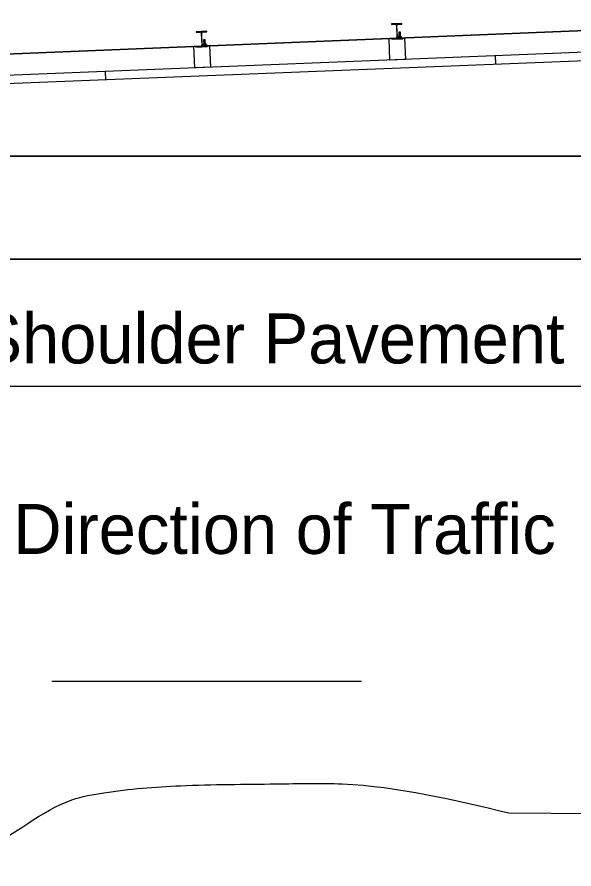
# Model space of a CAD drawing. Extents: x 8045 to 81668, y 6217 to 16762.
# Drawn here: x 11213.9 to 11392.2, y 9467.4 to 9740.2 of the extents above; entities that cross this region are included whole.
import ezdxf

# ---------------------------------------------------------------- set-up
doc = ezdxf.new("R2010")
doc.units = 0
for name, color, linetype in [('dsnStdLabel', 7, 'Continuous'), ('dsnStdNote', 7, 'Continuous'), ('dsnStdPattern', 7, 'Continuous'), ('Level 4', 7, 'Continuous')]:
    doc.layers.add(name, color=color, linetype=linetype)

msp = doc.modelspace()

# ---------------------------------------------------------------- linework, layer by layer
at = {"layer": 'dsnStdLabel'}
for p, q in [((11025.35, 9720.71), (11500.75, 9740.23)), ((11337.09, 9738.15), (11333.76, 9738.02)), ((11333.76, 9738.02), (11333.77, 9737.86)), ((11333.77, 9737.86), (11334.94, 9737.91)), ((11335.37, 9737.51), (11335.52, 9733.76)), ((11335.68, 9733.77), (11335.53, 9737.52)), ((11335.93, 9737.95), (11337.1, 9738)), ((11337.1, 9738), (11337.09, 9738.15)), ((11274.64, 9735.66), (11271.31, 9735.52)), ((11271.31, 9735.52), (11271.32, 9735.37)), ((11271.32, 9735.37), (11272.49, 9735.41)), ((11272.92, 9735.01), (11273.07, 9731.27)), ((11273.23, 9731.27), (11273.08, 9735.02)), ((11273.48, 9735.45), (11274.65, 9735.5)), ((11274.65, 9735.5), (11274.64, 9735.66)), ((11336.63, 9735.42), (11336.11, 9735.4)), ((11336.11, 9735.4), (11336.17, 9733.89)), ((11336.69, 9733.92), (11336.63, 9735.42)), ((11273.46, 9731.39), (11273.38, 9731.33)), ((11273.39, 9730.96), (11273.38, 9731.33)), ((11273.46, 9731.39), (11274.43, 9731.42)), ((11274.18, 9732.93), (11273.66, 9732.91)), ((11273.66, 9732.91), (11273.72, 9731.4)), ((11273.7, 9730.93), (11273.68, 9731.34)), ((11274.24, 9731.42), (11274.18, 9732.93)), ((11274.3, 9730.95), (11274.28, 9731.37)), ((11274.43, 9731.42), (11274.5, 9731.43)), ((11274.58, 9731.38), (11274.5, 9731.43)), ((11274.6, 9730.96), (11274.58, 9731.38)), ((11333.01, 9733.4), (11333.63, 9733.43)), ((11333.29, 9726.45), (11333.01, 9733.4)), ((11333.64, 9733.12), (11333.63, 9733.43)), ((11337.39, 9733.27), (11333.64, 9733.12)), ((11335.12, 9733.33), (11333.95, 9733.28)), ((11333.95, 9733.28), (11333.96, 9733.13)), ((11333.96, 9733.13), (11337.29, 9733.26)), ((11335.91, 9733.88), (11335.83, 9733.83)), ((11335.84, 9733.45), (11335.83, 9733.83)), ((11335.91, 9733.88), (11336.88, 9733.92)), ((11337.28, 9733.42), (11336.11, 9733.37)), ((11336.15, 9733.42), (11336.13, 9733.84)), ((11336.75, 9733.45), (11336.73, 9733.86)), ((11336.88, 9733.92), (11336.95, 9733.93)), ((11337.03, 9733.88), (11336.95, 9733.93)), ((11336.97, 9733.41), (11337.05, 9733.46)), ((11337.05, 9733.46), (11337.03, 9733.88)), ((11337.29, 9733.26), (11337.28, 9733.42)), ((11337.38, 9733.58), (11338, 9733.6)), ((11337.38, 9733.58), (11337.39, 9733.27)), ((11338, 9733.6), (11338.28, 9726.65)), ((11403.96, 9729.27), (10992.39, 9712.81)), ((11270.56, 9730.91), (11271.18, 9730.93)), ((11270.84, 9723.95), (11270.56, 9730.91)), ((11271.19, 9730.62), (11271.18, 9730.93)), ((11274.94, 9730.77), (11271.19, 9730.62)), ((11272.67, 9730.83), (11271.5, 9730.79)), ((11271.5, 9730.79), (11271.51, 9730.63)), ((11271.51, 9730.63), (11274.84, 9730.76)), ((11274.83, 9730.92), (11273.66, 9730.87)), ((11274.52, 9730.91), (11274.6, 9730.96)), ((11274.84, 9730.76), (11274.83, 9730.92)), ((11274.93, 9731.08), (11275.55, 9731.11)), ((11274.93, 9731.08), (11274.94, 9730.77)), ((11275.55, 9731.11), (11275.83, 9724.15)), ((11404.06, 9726.57), (10992.39, 9710.1)), ((11338.28, 9726.65), (11333.29, 9726.45)), ((11367.01, 9727.8), (11367.12, 9725.09)), ((11275.83, 9724.15), (11270.84, 9723.95)), ((11242.11, 9722.8), (11242.22, 9720.09)), ((10368.64, 9695.63), (11500.75, 9695.63)), ((10347.65, 9662.65), (11995.12, 9662.65)), ((11500.75, 9662.65), (10347.65, 9662.65)), ((10368.86, 9622), (11982.65, 9622)), ((11225.04, 9527.54), (11324.21, 9527.54)), ((11371.34, 9485.38), (11700.54, 9482.92))]:
    msp.add_line(p, q, dxfattribs=at)
for centre, start, end in [((11334.95, 9737.49), 2.2841, 92.2932), ((11335.94, 9737.53), 92.2981, 182.2871), ((11272.51, 9735), 2.2841, 92.2932), ((11273.49, 9735.04), 92.2981, 182.2871), ((11335.1, 9733.75), 272.2981, 2.2871), ((11336.09, 9733.79), 182.2841, 272.2932), ((11272.65, 9731.25), 272.2981, 2.2871), ((11273.64, 9731.29), 182.2841, 272.2932)]:
    msp.add_arc(centre, 0.417, start, end, dxfattribs=at)
for points in [[(11273.68, 9731.34), (11273.65, 9731.36), (11273.6, 9731.38), (11273.52, 9731.39), (11273.44, 9731.37), (11273.4, 9731.34), (11273.38, 9731.33)], [(11274.28, 9731.37), (11274.23, 9731.38), (11274.12, 9731.4), (11273.96, 9731.41), (11273.81, 9731.39), (11273.72, 9731.36), (11273.68, 9731.34)], [(11274.58, 9731.38), (11274.56, 9731.39), (11274.53, 9731.41), (11274.47, 9731.42), (11274.39, 9731.42), (11274.33, 9731.4), (11274.29, 9731.37), (11274.28, 9731.37)], [(11336.13, 9733.84), (11336.1, 9733.85), (11336.05, 9733.88), (11335.97, 9733.89), (11335.89, 9733.87), (11335.85, 9733.84), (11335.83, 9733.83)], [(11336.05, 9733.38), (11336.06, 9733.38), (11336.09, 9733.39), (11336.12, 9733.41), (11336.15, 9733.42)], [(11336.73, 9733.86), (11336.68, 9733.88), (11336.57, 9733.9), (11336.41, 9733.91), (11336.26, 9733.88), (11336.17, 9733.86), (11336.13, 9733.84)], [(11336.15, 9733.42), (11336.2, 9733.41), (11336.31, 9733.39), (11336.46, 9733.38), (11336.61, 9733.4), (11336.7, 9733.43), (11336.75, 9733.45)], [(11337.03, 9733.88), (11337.01, 9733.89), (11336.98, 9733.9), (11336.92, 9733.92), (11336.84, 9733.92), (11336.78, 9733.9), (11336.74, 9733.87), (11336.73, 9733.86)], [(11336.75, 9733.45), (11336.76, 9733.44), (11336.8, 9733.42), (11336.86, 9733.4), (11336.94, 9733.41), (11337, 9733.43), (11337.03, 9733.45), (11337.05, 9733.46)], [(11273.6, 9730.88), (11273.61, 9730.88), (11273.64, 9730.89), (11273.67, 9730.91), (11273.7, 9730.93)], [(11273.7, 9730.93), (11273.75, 9730.91), (11273.86, 9730.89), (11274.01, 9730.88), (11274.16, 9730.91), (11274.25, 9730.94), (11274.3, 9730.95)], [(11274.3, 9730.95), (11274.31, 9730.94), (11274.35, 9730.92), (11274.41, 9730.9), (11274.49, 9730.91), (11274.55, 9730.93), (11274.58, 9730.95), (11274.6, 9730.96)]]:
    msp.add_open_spline(points, degree=3, dxfattribs=at)
msp.add_spline([(10372.93, 9478.29), (10382.36, 9480.86), (10412.58, 9480.29), (10440.52, 9472.31), (10467.89, 9471.16), (10486.14, 9476.87), (10512.94, 9476.3), (10537.46, 9471.74), (10561.41, 9475.16), (10578.52, 9480.29), (10618.43, 9472.88), (10645.23, 9468.88), (10669.75, 9478.01), (10692.56, 9479.72), (10731.34, 9474.02), (10730.77, 9474.02), (10751.92, 9472.41), (10788.99, 9475.27), (10814.08, 9478.12), (10832.9, 9481.54), (10856.85, 9480.97), (10878.51, 9477.55), (10904.17, 9472.98), (10937.82, 9474.13), (10969.18, 9480.4), (10994.27, 9480.4), (11026.2, 9472.98), (11055.29, 9470.13), (11088.93, 9476.98), (11121.43, 9480.4), (11155.65, 9473.55), (11181.31, 9470.7), (11203.54, 9474.13), (11231.49, 9489.53), (11241.75, 9491.81), (11266.27, 9494.09), (11296.93, 9494.66), (11318.03, 9494.66), (11371.34, 9485.38)], degree=3, dxfattribs=at)
at = {"layer": 'dsnStdPattern'}
for p, q in [((11337.09, 9738.15), (11333.76, 9738.02)), ((11337.09, 9738.15), (11333.76, 9738.02)), ((11333.76, 9738.02), (11333.77, 9737.86)), ((11333.76, 9738.02), (11333.77, 9737.86)), ((11333.77, 9737.86), (11334.94, 9737.91)), ((11333.77, 9737.86), (11334.94, 9737.91)), ((11335.37, 9737.51), (11335.52, 9733.76)), ((11335.37, 9737.51), (11335.52, 9733.76)), ((11335.68, 9733.77), (11335.53, 9737.52)), ((11335.68, 9733.77), (11335.53, 9737.52)), ((11335.93, 9737.95), (11337.1, 9738)), ((11335.93, 9737.95), (11337.1, 9738)), ((11337.1, 9738), (11337.09, 9738.15)), ((11337.1, 9738), (11337.09, 9738.15)), ((11274.64, 9735.66), (11271.31, 9735.52)), ((11274.64, 9735.66), (11271.31, 9735.52)), ((11271.31, 9735.52), (11271.32, 9735.37)), ((11271.31, 9735.52), (11271.32, 9735.37)), ((11271.32, 9735.37), (11272.49, 9735.41)), ((11271.32, 9735.37), (11272.49, 9735.41)), ((11272.92, 9735.01), (11273.07, 9731.27)), ((11272.92, 9735.01), (11273.07, 9731.27)), ((11273.23, 9731.27), (11273.08, 9735.02)), ((11273.23, 9731.27), (11273.08, 9735.02)), ((11273.48, 9735.45), (11274.65, 9735.5)), ((11273.48, 9735.45), (11274.65, 9735.5)), ((11274.65, 9735.5), (11274.64, 9735.66)), ((11274.65, 9735.5), (11274.64, 9735.66)), ((11336.63, 9735.42), (11336.11, 9735.4)), ((11336.63, 9735.42), (11336.11, 9735.4)), ((11336.11, 9735.4), (11336.17, 9733.89)), ((11336.11, 9735.4), (11336.17, 9733.89)), ((11336.69, 9733.92), (11336.63, 9735.42)), ((11336.69, 9733.92), (11336.63, 9735.42)), ((11273.46, 9731.39), (11273.38, 9731.33)), ((11273.46, 9731.39), (11273.38, 9731.33)), ((11273.38, 9731.33), (11273.39, 9730.96)), ((11273.39, 9730.96), (11273.38, 9731.33)), ((11274.43, 9731.42), (11273.46, 9731.39)), ((11273.46, 9731.39), (11274.43, 9731.42)), ((11274.18, 9732.93), (11273.66, 9732.91)), ((11274.18, 9732.93), (11273.66, 9732.91)), ((11273.66, 9732.91), (11273.72, 9731.4)), ((11273.66, 9732.91), (11273.72, 9731.4)), ((11273.68, 9731.34), (11273.7, 9730.93)), ((11273.7, 9730.93), (11273.68, 9731.34)), ((11273.7, 9730.93), (11273.68, 9731.34)), ((11273.72, 9731.4), (11274.24, 9731.42)), ((11274.24, 9731.42), (11274.18, 9732.93)), ((11274.24, 9731.42), (11274.18, 9732.93)), ((11274.3, 9730.95), (11274.28, 9731.37)), ((11274.28, 9731.37), (11274.3, 9730.95)), ((11274.3, 9730.95), (11274.28, 9731.37)), ((11274.5, 9731.43), (11274.43, 9731.42)), ((11274.43, 9731.42), (11274.5, 9731.43)), ((11274.58, 9731.38), (11274.5, 9731.43)), ((11274.58, 9731.38), (11274.5, 9731.43)), ((11274.6, 9730.96), (11274.58, 9731.38)), ((11274.6, 9730.96), (11274.58, 9731.38)), ((11333.01, 9733.4), (11333.63, 9733.43)), ((11333.29, 9726.45), (11333.01, 9733.4)), ((11333.64, 9733.12), (11333.63, 9733.43)), ((11337.39, 9733.27), (11333.64, 9733.12)), ((11335.12, 9733.33), (11333.95, 9733.28)), ((11335.12, 9733.33), (11333.95, 9733.28)), ((11333.95, 9733.28), (11333.96, 9733.13)), ((11333.95, 9733.28), (11333.96, 9733.13)), ((11333.96, 9733.13), (11337.29, 9733.26)), ((11333.96, 9733.13), (11337.29, 9733.26)), ((11335.91, 9733.88), (11335.83, 9733.83)), ((11335.91, 9733.88), (11335.83, 9733.83)), ((11335.83, 9733.83), (11335.84, 9733.45)), ((11335.84, 9733.45), (11335.83, 9733.83)), ((11336.88, 9733.92), (11335.91, 9733.88)), ((11335.91, 9733.88), (11336.88, 9733.92)), ((11337.28, 9733.42), (11336.11, 9733.37)), ((11337.28, 9733.42), (11336.11, 9733.37)), ((11336.13, 9733.84), (11336.15, 9733.42)), ((11336.15, 9733.42), (11336.13, 9733.84)), ((11336.15, 9733.42), (11336.13, 9733.84)), ((11336.17, 9733.89), (11336.69, 9733.92)), ((11336.75, 9733.45), (11336.73, 9733.86)), ((11336.73, 9733.86), (11336.75, 9733.45)), ((11336.75, 9733.45), (11336.73, 9733.86)), ((11336.95, 9733.93), (11336.88, 9733.92)), ((11336.88, 9733.92), (11336.95, 9733.93)), ((11337.03, 9733.88), (11336.95, 9733.93)), ((11337.03, 9733.88), (11336.95, 9733.93)), ((11336.97, 9733.41), (11337.05, 9733.46)), ((11336.97, 9733.41), (11337.05, 9733.46)), ((11337.05, 9733.46), (11337.03, 9733.88)), ((11337.05, 9733.46), (11337.03, 9733.88)), ((11337.29, 9733.26), (11337.28, 9733.42)), ((11337.29, 9733.26), (11337.28, 9733.42)), ((11337.38, 9733.58), (11338, 9733.6)), ((11337.38, 9733.58), (11337.39, 9733.27)), ((11338, 9733.6), (11338.28, 9726.65)), ((11270.56, 9730.91), (11271.18, 9730.93)), ((11270.84, 9723.95), (11270.56, 9730.91)), ((11271.19, 9730.62), (11271.18, 9730.93)), ((11274.94, 9730.77), (11271.19, 9730.62)), ((11272.67, 9730.83), (11271.5, 9730.79)), ((11272.67, 9730.83), (11271.5, 9730.79)), ((11271.5, 9730.79), (11271.51, 9730.63)), ((11271.5, 9730.79), (11271.51, 9730.63)), ((11271.51, 9730.63), (11274.84, 9730.76)), ((11271.51, 9730.63), (11274.84, 9730.76)), ((11274.83, 9730.92), (11273.66, 9730.87)), ((11274.83, 9730.92), (11273.66, 9730.87)), ((11274.52, 9730.91), (11274.6, 9730.96)), ((11274.52, 9730.91), (11274.6, 9730.96)), ((11274.84, 9730.76), (11274.83, 9730.92)), ((11274.84, 9730.76), (11274.83, 9730.92)), ((11274.93, 9731.08), (11275.55, 9731.11)), ((11274.93, 9731.08), (11274.94, 9730.77)), ((11275.55, 9731.11), (11275.83, 9724.15)), ((11275.83, 9724.15), (11270.84, 9723.95))]:
    msp.add_line(p, q, dxfattribs=at)
for points in [[(11335.84, 9733.45), (11335.84, 9733.45)], [(11336.11, 9733.37), (11336.97, 9733.41), (11336.97, 9733.41)], [(11273.39, 9730.96), (11273.39, 9730.96)], [(11273.66, 9730.87), (11274.52, 9730.91), (11274.52, 9730.91)]]:
    msp.add_lwpolyline(points, dxfattribs=at)
for centre, start, end in [((11334.95, 9737.49), 2.2841, 92.2932), ((11334.95, 9737.49), 2.2841, 92.2932), ((11335.94, 9737.53), 92.2981, 182.2871), ((11335.94, 9737.53), 92.2981, 182.2871), ((11272.51, 9735), 2.2841, 92.2932), ((11272.51, 9735), 2.2841, 92.2932), ((11273.49, 9735.04), 92.2981, 182.2871), ((11273.49, 9735.04), 92.2981, 182.2871), ((11335.1, 9733.75), 272.2981, 2.2871), ((11335.1, 9733.75), 272.2981, 2.2871), ((11336.09, 9733.79), 182.2841, 272.2932), ((11336.09, 9733.79), 182.2841, 272.2932), ((11336.09, 9733.79), 233.1773, 272.2932), ((11272.65, 9731.25), 272.2981, 2.2871), ((11272.65, 9731.25), 272.2981, 2.2871), ((11273.64, 9731.29), 182.2841, 272.2932), ((11273.64, 9731.29), 182.2841, 272.2932), ((11273.64, 9731.29), 233.1773, 272.2932)]:
    msp.add_arc(centre, 0.417, start, end, dxfattribs=at)
for points in [[(11273.68, 9731.34), (11273.65, 9731.36), (11273.6, 9731.38), (11273.52, 9731.39), (11273.44, 9731.37), (11273.4, 9731.34), (11273.38, 9731.33)], [(11273.38, 9731.33), (11273.4, 9731.34), (11273.44, 9731.37), (11273.52, 9731.39), (11273.6, 9731.38), (11273.65, 9731.36), (11273.68, 9731.34)], [(11273.68, 9731.34), (11273.65, 9731.36), (11273.6, 9731.38), (11273.52, 9731.39), (11273.44, 9731.37), (11273.4, 9731.34), (11273.38, 9731.33)], [(11274.28, 9731.37), (11274.23, 9731.38), (11274.12, 9731.4), (11273.96, 9731.41), (11273.81, 9731.39), (11273.72, 9731.36), (11273.68, 9731.34)], [(11273.68, 9731.34), (11273.72, 9731.36), (11273.81, 9731.39), (11273.96, 9731.41), (11274.12, 9731.4), (11274.23, 9731.38), (11274.28, 9731.37)], [(11274.28, 9731.37), (11274.23, 9731.38), (11274.12, 9731.4), (11273.96, 9731.41), (11273.81, 9731.39), (11273.72, 9731.36), (11273.68, 9731.34)], [(11274.58, 9731.38), (11274.56, 9731.39), (11274.53, 9731.41), (11274.47, 9731.42), (11274.39, 9731.42), (11274.33, 9731.4), (11274.29, 9731.37), (11274.28, 9731.37)], [(11274.28, 9731.37), (11274.29, 9731.37), (11274.33, 9731.4), (11274.39, 9731.42), (11274.47, 9731.42), (11274.53, 9731.41), (11274.56, 9731.39), (11274.58, 9731.38)], [(11274.58, 9731.38), (11274.56, 9731.39), (11274.53, 9731.41), (11274.47, 9731.42), (11274.39, 9731.42), (11274.33, 9731.4), (11274.29, 9731.37), (11274.28, 9731.37)], [(11336.13, 9733.84), (11336.1, 9733.85), (11336.05, 9733.88), (11335.97, 9733.89), (11335.89, 9733.87), (11335.85, 9733.84), (11335.83, 9733.83)], [(11335.83, 9733.83), (11335.85, 9733.84), (11335.89, 9733.87), (11335.97, 9733.89), (11336.05, 9733.88), (11336.1, 9733.85), (11336.13, 9733.84)], [(11336.13, 9733.84), (11336.1, 9733.85), (11336.05, 9733.88), (11335.97, 9733.89), (11335.89, 9733.87), (11335.85, 9733.84), (11335.83, 9733.83)], [(11336.05, 9733.38), (11336.06, 9733.38), (11336.09, 9733.39), (11336.12, 9733.41), (11336.15, 9733.42)], [(11336.73, 9733.86), (11336.68, 9733.88), (11336.57, 9733.9), (11336.41, 9733.91), (11336.26, 9733.88), (11336.17, 9733.86), (11336.13, 9733.84)], [(11336.13, 9733.84), (11336.17, 9733.86), (11336.26, 9733.88), (11336.41, 9733.91), (11336.57, 9733.9), (11336.68, 9733.88), (11336.73, 9733.86)], [(11336.73, 9733.86), (11336.68, 9733.88), (11336.57, 9733.9), (11336.41, 9733.91), (11336.26, 9733.88), (11336.17, 9733.86), (11336.13, 9733.84)], [(11336.15, 9733.42), (11336.2, 9733.41), (11336.31, 9733.39), (11336.46, 9733.38), (11336.61, 9733.4), (11336.7, 9733.43), (11336.75, 9733.45)], [(11336.75, 9733.45), (11336.7, 9733.43), (11336.61, 9733.4), (11336.46, 9733.38), (11336.31, 9733.39), (11336.2, 9733.41), (11336.15, 9733.42)], [(11336.15, 9733.42), (11336.2, 9733.41), (11336.31, 9733.39), (11336.46, 9733.38), (11336.61, 9733.4), (11336.7, 9733.43), (11336.75, 9733.45)], [(11337.03, 9733.88), (11337.01, 9733.89), (11336.98, 9733.9), (11336.92, 9733.92), (11336.84, 9733.92), (11336.78, 9733.9), (11336.74, 9733.87), (11336.73, 9733.86)], [(11336.73, 9733.86), (11336.74, 9733.87), (11336.78, 9733.9), (11336.84, 9733.92), (11336.92, 9733.92), (11336.98, 9733.9), (11337.01, 9733.89), (11337.03, 9733.88)], [(11337.03, 9733.88), (11337.01, 9733.89), (11336.98, 9733.9), (11336.92, 9733.92), (11336.84, 9733.92), (11336.78, 9733.9), (11336.74, 9733.87), (11336.73, 9733.86)], [(11336.75, 9733.45), (11336.76, 9733.44), (11336.8, 9733.42), (11336.86, 9733.4), (11336.94, 9733.41), (11337, 9733.43), (11337.03, 9733.45), (11337.05, 9733.46)], [(11337.05, 9733.46), (11337.03, 9733.45), (11337, 9733.43), (11336.94, 9733.41), (11336.86, 9733.4), (11336.8, 9733.42), (11336.76, 9733.44), (11336.75, 9733.45)], [(11336.75, 9733.45), (11336.76, 9733.44), (11336.8, 9733.42), (11336.86, 9733.4), (11336.94, 9733.41), (11337, 9733.43), (11337.03, 9733.45), (11337.05, 9733.46)], [(11273.6, 9730.88), (11273.61, 9730.88), (11273.64, 9730.89), (11273.67, 9730.91), (11273.7, 9730.93)], [(11273.7, 9730.93), (11273.75, 9730.91), (11273.86, 9730.89), (11274.01, 9730.88), (11274.16, 9730.91), (11274.25, 9730.94), (11274.3, 9730.95)], [(11274.3, 9730.95), (11274.25, 9730.94), (11274.16, 9730.91), (11274.01, 9730.88), (11273.86, 9730.89), (11273.75, 9730.91), (11273.7, 9730.93)], [(11273.7, 9730.93), (11273.75, 9730.91), (11273.86, 9730.89), (11274.01, 9730.88), (11274.16, 9730.91), (11274.25, 9730.94), (11274.3, 9730.95)], [(11274.3, 9730.95), (11274.31, 9730.94), (11274.35, 9730.92), (11274.41, 9730.9), (11274.49, 9730.91), (11274.55, 9730.93), (11274.58, 9730.95), (11274.6, 9730.96)], [(11274.6, 9730.96), (11274.58, 9730.95), (11274.55, 9730.93), (11274.49, 9730.91), (11274.41, 9730.9), (11274.35, 9730.92), (11274.31, 9730.94), (11274.3, 9730.95)], [(11274.3, 9730.95), (11274.31, 9730.94), (11274.35, 9730.92), (11274.41, 9730.9), (11274.49, 9730.91), (11274.55, 9730.93), (11274.58, 9730.95), (11274.6, 9730.96)]]:
    msp.add_open_spline(points, degree=3, dxfattribs=at)
at = {"layer": 'Level 4'}
for p, q in [((11454.21, 9738.32), (11025.35, 9720.71)), ((10526.39, 9695.63), (11500.75, 9695.63)), ((11558.3, 9695.63), (10526.39, 9695.63))]:
    msp.add_line(p, q, dxfattribs=at)

# ---------------------------------------------------------------- texts
at = {"layer": 'dsnStdNote'}
for s, p in [('Edge of Shoulder Pavement', (11121.57, 9629.3)), ('Edge of Shoulder Pavement', (11121.57, 9629.3)), ('Direction of Traffic', (11212.76, 9568.31)), ('Direction of Traffic', (11212.76, 9568.31))]:
    msp.add_text(s, height=16, dxfattribs=at).set_placement(p)

doc.saveas('drawing.dxf')
